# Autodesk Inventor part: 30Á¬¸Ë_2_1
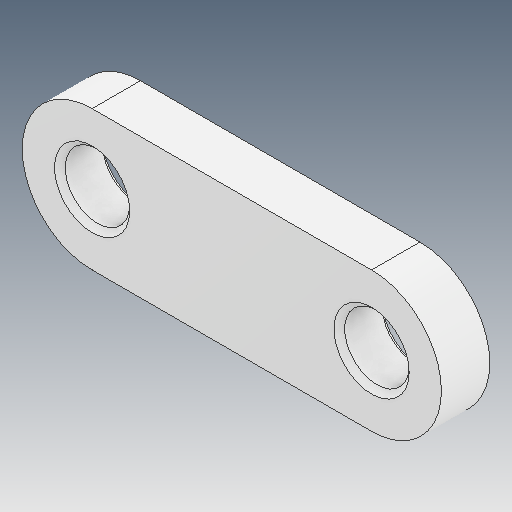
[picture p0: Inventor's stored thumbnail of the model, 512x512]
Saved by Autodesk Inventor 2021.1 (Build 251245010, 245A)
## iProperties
Created: 2021-05
Part Number: 30Á¬¸Ë_2_1
Material: Ogólny
Document SubType Name: Modeling
Designer: user
Density: 1 g/cm^3
Appearance: Domyślna
Author: user
Revision Number: ÈÎºÎ
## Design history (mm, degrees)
feature "ÊäÈë1"
node "Bryła1"
